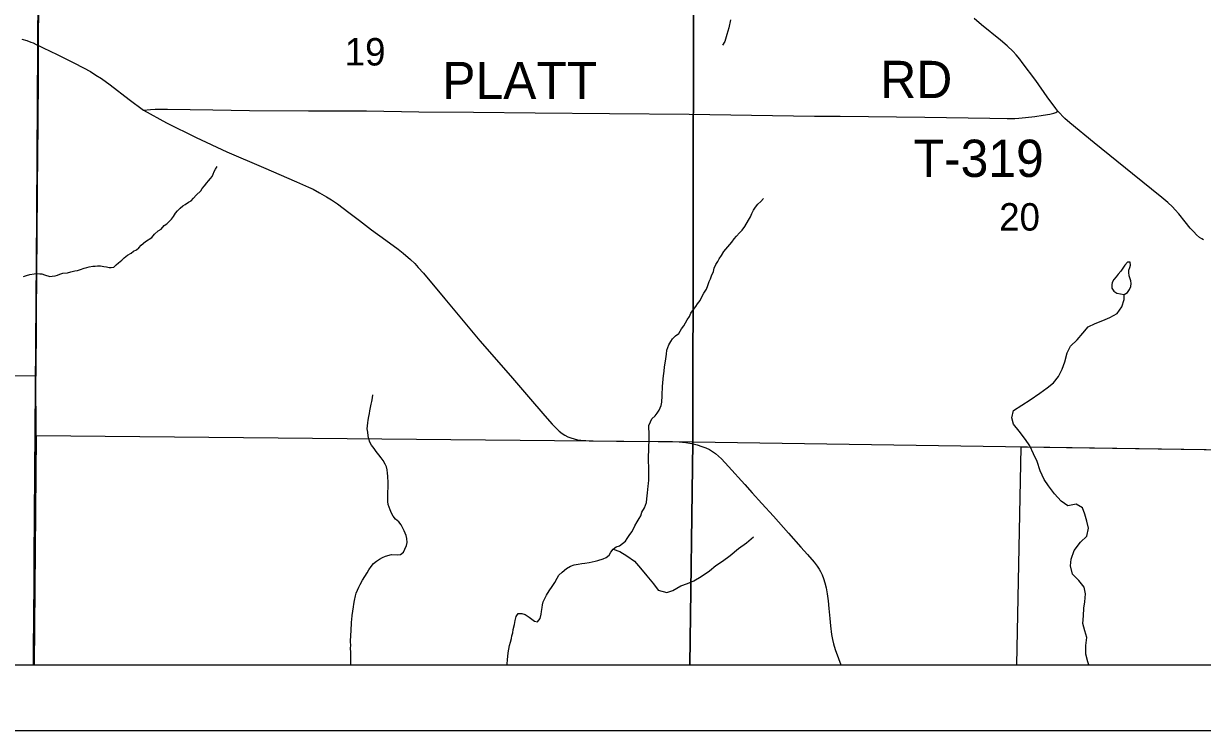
# Model space of a CAD drawing. Extents: x -8.8 to 41.4, y 0 to 34.6.
# Drawn here: x 5.315 to 7.113, y 14 to 15.077 of the extents above; entities that cross this region are included whole.
import ezdxf

# ---------------------------------------------------------------- set-up
doc = ezdxf.new("R2010")
doc.units = 0
for name, color, linetype in [('GM_X_Corporation', 7, 'Continuous'), ('GM_X_County_Road', 7, 'Continuous'), ('GM_X_Minor_Lake', 7, 'Continuous'), ('GM_X_Minor_River', 7, 'Continuous'), ('GM_X_Section_Text', 7, 'Continuous'), ('GM_X_Township_Road', 7, 'Continuous'), ('GM_X_Township_Text', 7, 'Continuous'), ('SH_Border', 7, 'Continuous')]:
    doc.layers.add(name, color=color, linetype=linetype)

msp = doc.modelspace()

# ---------------------------------------------------------------- linework, layer by layer
at = {"layer": 'GM_X_Corporation'}
for points in [[(2.1, 14.1), (5.3301, 14.1), (5.3311, 14.2265), (5.3314, 14.2618), (5.3339, 14.5882), (5.3375, 15.0446), (5.3393, 15.3164), (5.3461, 16.3507), (5.3531, 16.5483), (5.3614, 17.3836), (5.3735, 18.6369), (5.3735, 18.6421), (5.3723, 18.6421), (5.2807, 18.6436)], [(5.3614, 17.3836), (5.3531, 16.5483), (5.3461, 16.3507), (5.3393, 15.3164), (5.3375, 15.0446), (5.3339, 14.5882), (5.3314, 14.2618), (5.3311, 14.2265), (5.3301, 14.1), (8.9, 14.1), (8.9, 18.5906)]]:
    msp.add_lwpolyline(points, dxfattribs=at)
for points in [[(4.3264, 15.5667), (5.3394, 15.5503), (5.3392, 15.4586), (5.3337, 14.5401), (4.3237, 14.5538)], [(5.3392, 15.4586), (6.3374, 15.4422), (6.336, 14.4395), (5.3342, 14.4488), (5.3337, 14.5401)], [(6.3374, 15.4422), (7.3307, 15.4293), (7.3236, 14.4245), (6.336, 14.4395)], [(4.3207, 14.1), (5.3314, 14.1), (5.3342, 14.4488), (5.3337, 14.5401), (4.3237, 14.5538)], [(5.3314, 14.1), (6.3313, 14.1), (6.336, 14.4395), (5.3342, 14.4488)], [(6.3313, 14.1), (7.3207, 14.1), (7.3236, 14.4245), (6.336, 14.4395)], [(6.8296, 14.1), (7.3217, 14.1), (7.3218, 14.1076), (7.3234, 14.2324), (7.3251, 14.3764), (7.3255, 14.4247), (6.8363, 14.4315)]]:
    msp.add_lwpolyline(points, close=True, dxfattribs=at)
at = {"layer": 'GM_X_County_Road'}
for points in [[(5.3301, 14.1), (5.3302, 14.1222), (5.3314, 14.2259), (5.3315, 14.2378), (5.3316, 14.2612), (5.3322, 14.3474), (5.3326, 14.4306), (5.3338, 14.5496), (5.3342, 14.5876), (5.3349, 14.6539), (5.3354, 14.6999), (5.3358, 14.7507), (5.3366, 14.8278), (5.3374, 14.9246), (5.3379, 14.9991), (5.3379, 15.0351), (5.3377, 15.044), (5.3374, 15.0557), (5.3376, 15.0904)], [(7.1151, 14.7478), (7.1125, 14.7492), (7.1089, 14.7515), (7.1044, 14.7553), (7.1003, 14.7598), (7.0949, 14.7658), (7.0872, 14.7753), (7.0774, 14.7874), (7.0721, 14.7936), (7.0677, 14.7981), (7.0605, 14.8049), (7.0514, 14.8126), (7.0068, 14.8485), (6.9484, 14.8956), (6.9114, 14.926), (6.9036, 14.933), (6.8931, 14.9442), (6.89, 14.9481), (6.8766, 14.9659), (6.8591, 14.9909), (6.8387, 15.0183), (6.835, 15.0232), (6.8293, 15.03), (6.8248, 15.0351), (6.8155, 15.0435), (6.8053, 15.0524), (6.7766, 15.0755), (6.7652, 15.0853)], [(5.3127, 15.0537), (5.3199, 15.0515), (5.326, 15.0493), (5.3297, 15.0479), (5.3344, 15.0457), (5.3377, 15.044)], [(5.3377, 15.044), (5.3448, 15.0406), (5.3666, 15.0304), (5.3918, 15.0176), (5.4067, 15.0099), (5.417, 15.0042), (5.4255, 14.9991), (5.4341, 14.9937), (5.447, 14.9842), (5.4761, 14.9617), (5.4981, 14.9456), (5.5333, 14.926), (5.5786, 14.904), (5.6253, 14.882), (5.6812, 14.8579), (5.7317, 14.8362), (5.7496, 14.8283), (5.7568, 14.8249), (5.7667, 14.8197), (5.7774, 14.8135), (5.7847, 14.8089), (5.7939, 14.8025), (5.8114, 14.7897), (5.8277, 14.7772), (5.846, 14.7633), (5.8675, 14.7475), (5.8864, 14.7334), (5.8942, 14.7273), (5.9056, 14.7177), (5.9118, 14.7117), (5.9173, 14.7059), (5.925, 14.697), (5.9575, 14.6578), (6.0112, 14.5941), (6.0577, 14.5406), (6.0854, 14.5087), (6.1105, 14.4795), (6.1215, 14.4669), (6.1275, 14.4605), (6.1321, 14.4562), (6.1365, 14.4526), (6.1408, 14.4499), (6.1453, 14.4476), (6.15, 14.4458), (6.1548, 14.4443), (6.1603, 14.4431), (6.1653, 14.4424), (6.1728, 14.4418), (6.184, 14.4414), (6.2194, 14.4411), (6.3049, 14.4403), (6.3154, 14.4397), (6.3254, 14.4388), (6.3345, 14.4374), (6.3427, 14.4353), (6.35, 14.4329), (6.3558, 14.4307), (6.3613, 14.428), (6.3661, 14.4252), (6.3706, 14.422), (6.3752, 14.4181), (6.3797, 14.4138), (6.3907, 14.4022), (6.4154, 14.3749), (6.4267, 14.3621), (6.4412, 14.346), (6.4589, 14.3264), (6.4821, 14.3004), (6.501, 14.2794), (6.5109, 14.2679), (6.5212, 14.2563), (6.5258, 14.2505), (6.5288, 14.2459), (6.5309, 14.2421), (6.5333, 14.2372), (6.5355, 14.2314), (6.5375, 14.225), (6.5393, 14.2172), (6.541, 14.208), (6.5423, 14.1976), (6.5435, 14.1859), (6.545, 14.1704), (6.5461, 14.1593), (6.5478, 14.1464), (6.5493, 14.1384), (6.5509, 14.1317), (6.5534, 14.1233), (6.5581, 14.1098), (6.5619, 14.1)]]:
    msp.add_lwpolyline(points, dxfattribs=at)
at = {"layer": 'GM_X_Minor_Lake'}
msp.add_line((6.9829, 14.6665), (6.9939, 14.6643), dxfattribs=at)
msp.add_lwpolyline([(6.9939, 14.6643), (6.9989, 14.6675), (7.0021, 14.672), (7.0041, 14.6769), (7.0046, 14.6814), (7.004, 14.6853), (7.0019, 14.6929), (7.0013, 14.6979), (7.0014, 14.7017), (7.0026, 14.7054), (7.0035, 14.7092), (7.0033, 14.7138), (6.9991, 14.7139), (6.9952, 14.7091), (6.9888, 14.7001), (6.9849, 14.6953), (6.9818, 14.6916), (6.9782, 14.6875), (6.9758, 14.683), (6.975, 14.6792), (6.9752, 14.6739), (6.9785, 14.6696), (6.9829, 14.6665)], dxfattribs=at)
at = {"layer": 'GM_X_Minor_River'}
for points in [[(6.3936, 15.0832), (6.3909, 15.0711), (6.388, 15.0609), (6.3847, 15.05), (6.3815, 15.0444)], [(5.4209, 14.7076), (5.4243, 14.7079), (5.4281, 14.7082), (5.4327, 14.7081), (5.4376, 14.7072), (5.4417, 14.7067), (5.4455, 14.7058), (5.4489, 14.7057), (5.4527, 14.7064), (5.4563, 14.7097), (5.4597, 14.7126), (5.4648, 14.717), (5.4687, 14.7204), (5.4737, 14.7244), (5.4791, 14.7277), (5.483, 14.7306), (5.4876, 14.7327), (5.4911, 14.7357), (5.4947, 14.7398), (5.5009, 14.7453), (5.5106, 14.7515), (5.5149, 14.7563), (5.5207, 14.7614), (5.5249, 14.764), (5.5297, 14.7696), (5.5335, 14.7721), (5.5409, 14.7791), (5.5437, 14.7832), (5.5469, 14.7884), (5.55, 14.7918), (5.5539, 14.7962), (5.5582, 14.7995), (5.5617, 14.8017), (5.5667, 14.8054), (5.5706, 14.8075), (5.5745, 14.8116), (5.5784, 14.8161), (5.5854, 14.8227), (5.5878, 14.8261), (5.591, 14.8301), (5.5945, 14.8346), (5.5972, 14.8379), (5.6004, 14.8413), (5.6027, 14.8446), (5.6044, 14.848), (5.606, 14.8518), (5.608, 14.8555), (5.6104, 14.8596)], [(6.2889, 14.5002), (6.2893, 14.51), (6.2891, 14.515), (6.2896, 14.5203), (6.2898, 14.5245), (6.2903, 14.5294), (6.2909, 14.5358), (6.2915, 14.5404), (6.2925, 14.5476), (6.2927, 14.5544), (6.2937, 14.5597), (6.2947, 14.5662), (6.2957, 14.5737), (6.2966, 14.5794), (6.2979, 14.5836), (6.2996, 14.5877), (6.3024, 14.5926), (6.3052, 14.5967), (6.3098, 14.6015), (6.3145, 14.6051), (6.3188, 14.6119), (6.3224, 14.6167), (6.3248, 14.6212), (6.3276, 14.6261), (6.3308, 14.6309), (6.3329, 14.6358), (6.3372, 14.6418), (6.3404, 14.6462), (6.3431, 14.6503), (6.3471, 14.6555), (6.3503, 14.6619), (6.3527, 14.6664), (6.3567, 14.6724), (6.3588, 14.6784), (6.3609, 14.6841), (6.3629, 14.6882), (6.3646, 14.6931), (6.3675, 14.6995), (6.3688, 14.7044), (6.3712, 14.7104), (6.374, 14.7149), (6.3764, 14.719), (6.3796, 14.7238), (6.3836, 14.7298), (6.3954, 14.7443), (6.3989, 14.7491), (6.4028, 14.7536), (6.4071, 14.7584), (6.4114, 14.7628), (6.4154, 14.7681), (6.421, 14.7778), (6.4238, 14.783), (6.4262, 14.7879), (6.4287, 14.7932), (6.4318, 14.7976), (6.4354, 14.8021), (6.44, 14.8061), (6.444, 14.8106)], [(5.315, 14.692), (5.3196, 14.6934), (5.3245, 14.6948), (5.3314, 14.6961), (5.3356, 14.6964), (5.3398, 14.6962), (5.3432, 14.6958), (5.3469, 14.6945), (5.3552, 14.692), (5.359, 14.6923), (5.3632, 14.6929), (5.367, 14.694), (5.3705, 14.6954), (5.3751, 14.6968), (5.3819, 14.6977), (5.3873, 14.6991), (5.3934, 14.7004), (5.3976, 14.7011), (5.4018, 14.7025), (5.4075, 14.7046), (5.4114, 14.7056), (5.4152, 14.7067), (5.4209, 14.7076)], [(6.9401, 14.1), (6.9388, 14.1047), (6.9357, 14.1162), (6.9357, 14.1295), (6.9372, 14.1416), (6.9341, 14.1516), (6.931, 14.1631), (6.932, 14.1748), (6.9327, 14.1862), (6.9342, 14.196), (6.9353, 14.2082), (6.9329, 14.2181), (6.9248, 14.2286), (6.9152, 14.238), (6.9122, 14.251), (6.9132, 14.2608), (6.9177, 14.274), (6.9272, 14.2867), (6.9369, 14.2959), (6.9399, 14.3083), (6.9372, 14.319), (6.9341, 14.3294), (6.9306, 14.3394), (6.9209, 14.345), (6.9083, 14.3423), (6.8982, 14.3494), (6.8879, 14.3607), (6.8788, 14.3727), (6.8722, 14.3824), (6.8661, 14.3955), (6.8616, 14.4097), (6.8555, 14.4217), (6.8501, 14.4336), (6.8436, 14.4436), (6.8337, 14.4561), (6.8252, 14.4666), (6.8225, 14.4765), (6.8254, 14.4875), (6.8382, 14.4958), (6.8509, 14.5038), (6.8652, 14.5141), (6.8765, 14.5221), (6.8862, 14.5298), (6.8937, 14.5395), (6.8993, 14.5507), (6.9038, 14.562), (6.9072, 14.5755), (6.9124, 14.5857), (6.9225, 14.5952), (6.9312, 14.6056), (6.939, 14.6153), (6.9498, 14.6203), (6.9617, 14.6249), (6.9724, 14.6295), (6.9836, 14.6353), (6.9903, 14.6457), (6.9941, 14.657), (6.9939, 14.6643)], [(5.871, 14.362), (5.8713, 14.3715), (5.8711, 14.3776), (5.8707, 14.3875), (5.8705, 14.392), (5.8696, 14.397), (5.8686, 14.4016), (5.8669, 14.4058), (5.8637, 14.4112), (5.8605, 14.4155), (5.8569, 14.4202), (5.8529, 14.4252), (5.8497, 14.4299), (5.8458, 14.435), (5.8433, 14.4396), (5.842, 14.4446), (5.841, 14.4488), (5.8401, 14.4545), (5.8395, 14.4595), (5.84, 14.4644), (5.8402, 14.4686), (5.8407, 14.4731), (5.8417, 14.4784), (5.8426, 14.483), (5.8435, 14.4871), (5.8444, 14.492), (5.8454, 14.4973), (5.8463, 14.5015), (5.8472, 14.5072), (5.8478, 14.5117)], [(6.0525, 14.1), (6.0526, 14.1015), (6.0532, 14.1076), (6.0543, 14.1182), (6.0556, 14.1239), (6.0566, 14.1296), (6.0579, 14.1345), (6.0592, 14.1401), (6.0601, 14.1443), (6.0614, 14.1488), (6.0619, 14.1537), (6.0641, 14.1613), (6.0651, 14.1673), (6.0664, 14.1734), (6.0696, 14.1782), (6.0752, 14.1781), (6.0801, 14.1768), (6.0863, 14.1724), (6.0907, 14.1693), (6.0947, 14.1665), (6.0992, 14.1656), (6.1031, 14.1704), (6.1049, 14.1772), (6.1054, 14.1814), (6.1064, 14.1871), (6.1069, 14.1916), (6.1078, 14.1962), (6.113, 14.2059), (6.117, 14.2126), (6.1214, 14.2193), (6.1254, 14.2253), (6.129, 14.2321), (6.1318, 14.2365), (6.1369, 14.2413), (6.1434, 14.2469), (6.1496, 14.2505), (6.1549, 14.2526), (6.161, 14.2536), (6.1666, 14.2542), (6.1715, 14.2548), (6.178, 14.2557), (6.187, 14.2578), (6.1912, 14.2588), (6.1992, 14.2616), (6.2038, 14.2634), (6.2084, 14.267), (6.2108, 14.2715), (6.2144, 14.2764), (6.219, 14.2797), (6.224, 14.2814), (6.2286, 14.2847), (6.2332, 14.2884), (6.236, 14.2925), (6.2392, 14.297), (6.2428, 14.3026), (6.2456, 14.307), (6.2476, 14.3119), (6.2512, 14.3179), (6.2544, 14.3231), (6.2568, 14.3273), (6.2585, 14.3325), (6.2621, 14.3393), (6.2641, 14.3434), (6.2654, 14.3475), (6.266, 14.3532), (6.2665, 14.3574), (6.2671, 14.362), (6.2676, 14.3673), (6.2678, 14.3722), (6.2683, 14.3764), (6.2689, 14.3813), (6.2692, 14.39), (6.269, 14.3961), (6.2688, 14.4011), (6.2684, 14.4102), (6.2682, 14.4152), (6.2693, 14.4444), (6.2695, 14.4497), (6.2693, 14.4551), (6.2687, 14.4597), (6.2692, 14.465), (6.2713, 14.4702), (6.2737, 14.4747), (6.2784, 14.4795), (6.2819, 14.4836), (6.2847, 14.4881), (6.2876, 14.4952), (6.2889, 14.5002)], [(5.8145, 14.1), (5.8144, 14.1046), (5.8143, 14.1129), (5.8142, 14.119), (5.814, 14.1247), (5.8142, 14.1301), (5.814, 14.135), (5.8144, 14.1457), (5.8149, 14.151), (5.8154, 14.165), (5.8159, 14.1692), (5.8165, 14.1753), (5.8185, 14.1881), (5.819, 14.1923), (5.82, 14.198), (5.8214, 14.2052), (5.8226, 14.2093), (5.8243, 14.2138), (5.8264, 14.2183), (5.8284, 14.2225), (5.832, 14.2288), (5.8392, 14.24), (5.8419, 14.2445), (5.8455, 14.2497), (5.8491, 14.2542), (5.8533, 14.2579), (5.8583, 14.2612), (5.8625, 14.2637), (5.8671, 14.2658), (5.8762, 14.2679), (5.8852, 14.2676), (5.8901, 14.2682), (5.8948, 14.2719), (5.8968, 14.2764), (5.8993, 14.2816), (5.9002, 14.2866), (5.8996, 14.2923), (5.8987, 14.2969), (5.8959, 14.3042), (5.8938, 14.3084), (5.891, 14.3131), (5.8874, 14.3177), (5.8827, 14.3221), (5.8791, 14.3264), (5.8766, 14.331), (5.8742, 14.336), (5.8715, 14.3445), (5.8709, 14.349), (5.8706, 14.3532), (5.8708, 14.3574), (5.871, 14.362)], [(6.2144, 14.2764), (6.2248, 14.2725), (6.2356, 14.2662), (6.2471, 14.2579), (6.2563, 14.2473), (6.2659, 14.2357), (6.2761, 14.2236), (6.2831, 14.2139), (6.2963, 14.2101), (6.3058, 14.2133), (6.3178, 14.2205), (6.3278, 14.224), (6.3377, 14.2279), (6.3489, 14.2348), (6.3613, 14.2432), (6.3714, 14.2513), (6.3814, 14.2582), (6.3931, 14.2666), (6.4059, 14.2773), (6.4179, 14.2861), (6.4288, 14.2949)]]:
    msp.add_lwpolyline(points, dxfattribs=at)
at = {"layer": 'GM_X_Township_Road'}
msp.add_lwpolyline([(5.4981, 14.9456), (5.509, 14.9467), (5.5157, 14.9472), (5.5347, 14.9468), (5.6037, 14.9458), (5.6596, 14.9451), (5.7498, 14.9443), (5.8383, 14.9443), (5.9179, 14.9431), (6.0016, 14.9423), (6.0958, 14.9416), (6.2089, 14.9402), (6.3307, 14.9392), (6.4254, 14.938), (6.5219, 14.9366), (6.5609, 14.9365), (6.6901, 14.9349), (6.7889, 14.9334), (6.8156, 14.9328), (6.8274, 14.933), (6.8336, 14.9334), (6.8435, 14.9343), (6.8576, 14.936), (6.8705, 14.9378), (6.8809, 14.9394), (6.8869, 14.9409), (6.8899, 14.942), (6.8931, 14.9442)], dxfattribs=at)
at = {"layer": 'SH_Border'}
for p, q in [((2.1, 14.1), (8.9, 14.1)), ((2, 14), (9, 14))]:
    msp.add_line(p, q, dxfattribs=at)

# ---------------------------------------------------------------- texts
at = {"layer": 'GM_X_Section_Text'}
for s, p in [('PLATT', (5.9538, 14.9623)), ('RD', (6.6221, 14.9639)), ('T-319', (6.6729, 14.8437))]:
    msp.add_text(s, height=0.05682, rotation=0, dxfattribs=at).set_placement(p)
at = {"layer": 'GM_X_Township_Text'}
for s, p in [('19', (5.805, 15.0136)), ('20', (6.8034, 14.7619))]:
    msp.add_text(s, height=0.04186, rotation=0, dxfattribs=at).set_placement(p)

doc.saveas('drawing.dxf')
